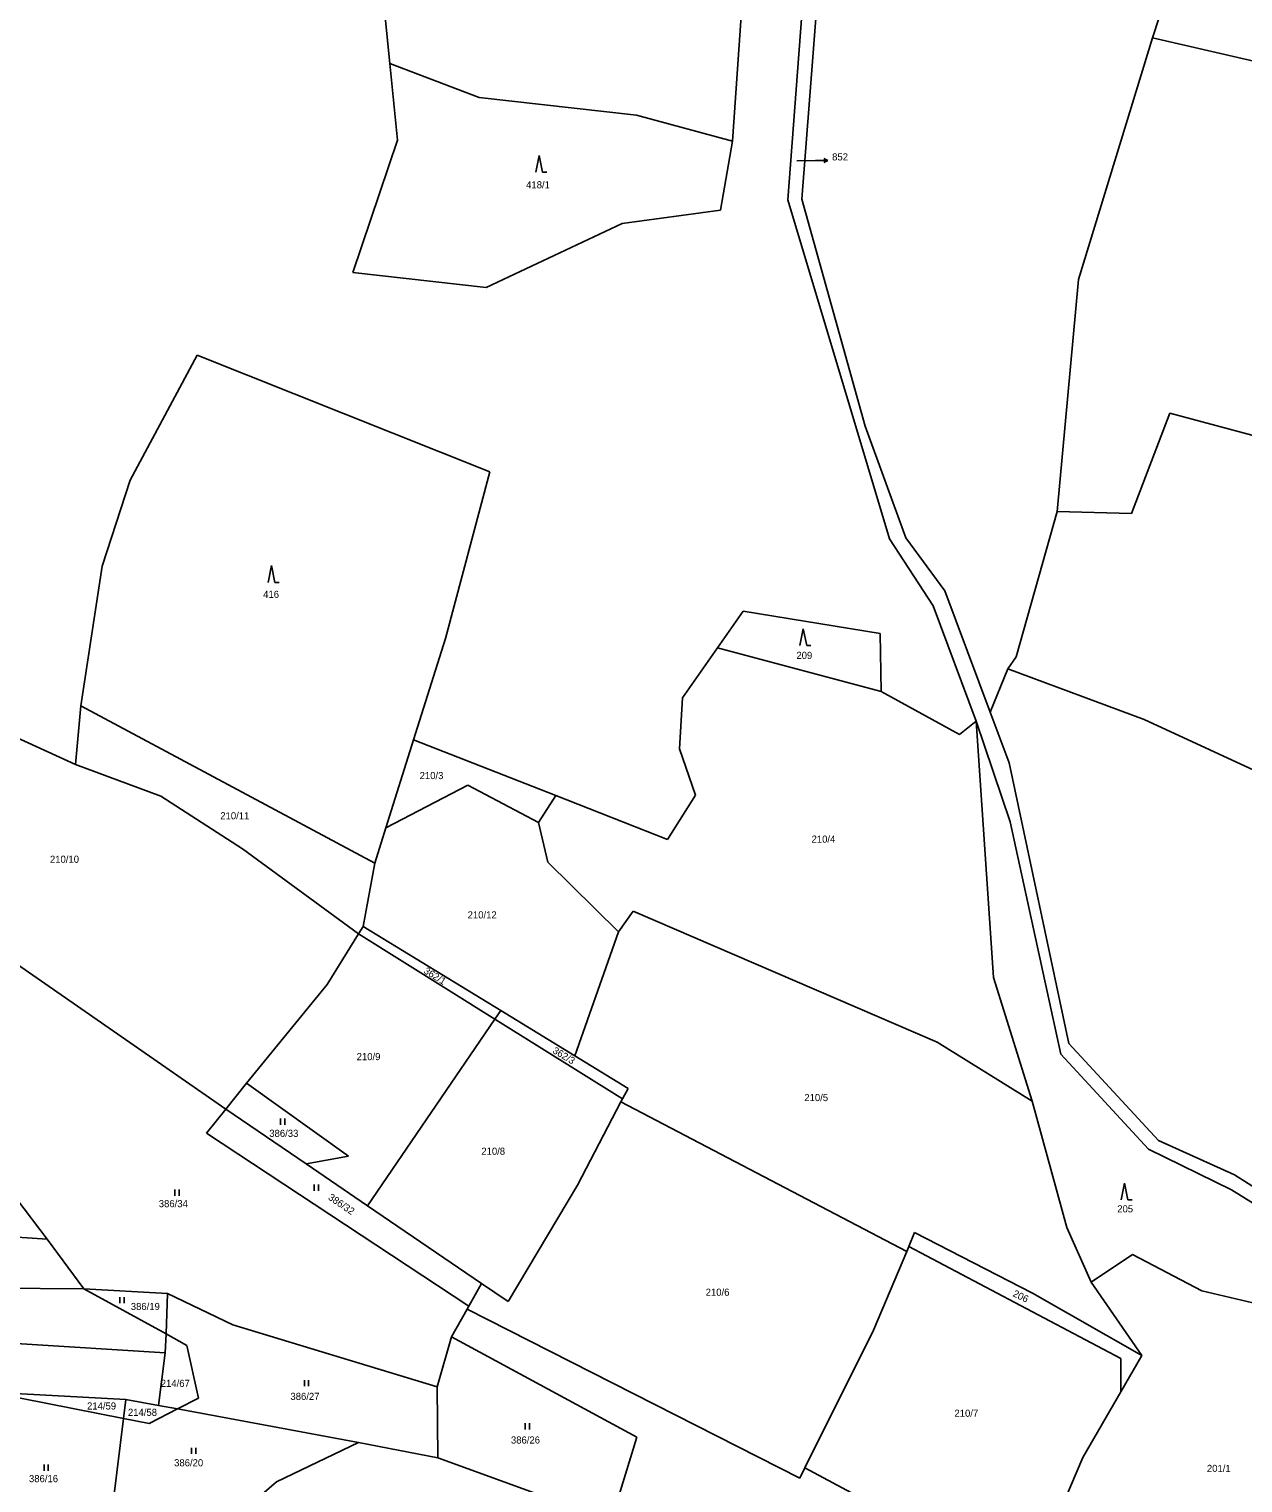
# Model space of a CAD drawing. Extents: x -791032 to -787751, y -1106872 to -1104403.
# Drawn here: x -789521.6 to -789231, y -1105047.4 to -1104699.4 of the extents above; entities that cross this region are included whole.
import ezdxf

# ---------------------------------------------------------------- set-up
doc = ezdxf.new("R2010")
doc.units = 0
for name, color, linetype in [('Komunikace', 7, 'Continuous'), ('Vrstva 1', 7, 'Continuous'), ('Vrstva 14', 7, 'Continuous'), ('Vrstva 16', 7, 'Continuous'), ('Vrstva 23', 7, 'Continuous')]:
    doc.layers.add(name, color=color, linetype=linetype)

msp = doc.modelspace()

# ---------------------------------------------------------------- linework, layer by layer
at = {"layer": 'Komunikace'}
msp.add_line((-789337.83, -1104730.99), (-789333.38, -1104730.91), dxfattribs=at)
at = {"layer": 'Vrstva 1'}
for p, q in [((-789252.66, -1104701.48), (-789219.82, -1104600.12)), ((-789332.71, -1104644.49), (-789339.98, -1104740.32)), ((-789336.62, -1104740.1), (-789329.28, -1104644.72)), ((-789439.94, -1104660.34), (-789435.24, -1104707.64)), ((-789353.27, -1104726.21), (-789350.23, -1104682.32)), ((-789270.39, -1104759.38), (-789252.66, -1104701.48)), ((-789252.66, -1104701.48), (-789130.29, -1104729.79)), ((-789435.24, -1104707.64), (-789413.89, -1104715.81)), ((-789435.24, -1104707.64), (-789433.41, -1104726)), ((-789413.89, -1104715.81), (-789376.18, -1104720)), ((-789376.18, -1104720), (-789353.27, -1104726.21)), ((-789433.41, -1104726), (-789444.13, -1104757.69)), ((-789356.1, -1104742.74), (-789353.27, -1104726.21)), ((-789339.98, -1104740.32), (-789315.67, -1104821.46)), ((-789321.51, -1104794.47), (-789336.62, -1104740.1)), ((-789379.64, -1104745.93), (-789356.1, -1104742.74)), ((-789412.24, -1104761.29), (-789379.64, -1104745.93)), ((-789444.13, -1104757.69), (-789412.24, -1104761.29)), ((-789270.39, -1104759.38), (-789275.52, -1104814.86)), ((-789497.43, -1104807.38), (-789481.42, -1104777.44)), ((-789481.42, -1104777.44), (-789411.33, -1104805.4)), ((-789257.76, -1104815.39), (-789248.58, -1104791.34)), ((-789248.58, -1104791.34), (-789141.03, -1104820.32)), ((-789311.76, -1104821.17), (-789321.51, -1104794.47)), ((-789411.33, -1104805.4), (-789421.97, -1104845.28)), ((-789504.1, -1104828), (-789497.43, -1104807.38)), ((-789275.52, -1104814.86), (-789285.31, -1104849.64)), ((-789275.52, -1104814.86), (-789257.76, -1104815.39)), ((-789315.67, -1104821.46), (-789305.23, -1104837.5)), ((-789302.4, -1104833.9), (-789311.76, -1104821.17)), ((-789509.25, -1104861.37), (-789504.1, -1104828)), ((-789291.52, -1104862.89), (-789302.4, -1104833.9)), ((-789305.23, -1104837.5), (-789294.92, -1104865.1)), ((-789356.8, -1104847.54), (-789350.66, -1104838.78)), ((-789350.66, -1104838.78), (-789317.89, -1104844.12)), ((-789317.89, -1104844.12), (-789317.68, -1104857.94)), ((-789421.97, -1104845.28), (-789429.6, -1104869.53)), ((-789365.17, -1104859.46), (-789356.8, -1104847.54)), ((-789317.68, -1104857.94), (-789356.8, -1104847.54)), ((-789285.31, -1104849.64), (-789287.33, -1104852.58)), ((-789287.33, -1104852.58), (-789291.52, -1104862.89)), ((-789254.72, -1104864.68), (-789287.33, -1104852.58)), ((-789298.88, -1104868.28), (-789317.68, -1104857.94)), ((-789510.51, -1104875.41), (-789509.25, -1104861.37)), ((-789438.89, -1104899.05), (-789509.25, -1104861.37)), ((-789365.17, -1104859.46), (-789365.96, -1104871.69)), ((-789533.85, -1104864.78), (-789510.51, -1104875.41)), ((-789294.92, -1104865.1), (-789298.88, -1104868.28)), ((-789294.92, -1104865.1), (-789286.73, -1104889.2)), ((-789290.79, -1104926.4), (-789294.92, -1104865.1)), ((-789286.98, -1104875.01), (-789291.52, -1104862.89)), ((-789144.83, -1104915.36), (-789254.72, -1104864.68)), ((-789429.6, -1104869.53), (-789436.24, -1104890.62)), ((-789395.55, -1104882.88), (-789429.6, -1104869.53)), ((-789365.96, -1104871.69), (-789362.12, -1104882.76)), ((-789510.51, -1104875.41), (-789490.08, -1104883.03)), ((-789272.7, -1104942.21), (-789286.98, -1104875.01)), ((-789490.08, -1104883.03), (-789470.54, -1104895.61)), ((-789416.63, -1104880.38), (-789436.24, -1104890.62)), ((-789416.63, -1104880.38), (-789399.67, -1104889.33)), ((-789399.67, -1104889.33), (-789395.55, -1104882.88)), ((-789368.81, -1104893.37), (-789395.55, -1104882.88)), ((-789362.12, -1104882.76), (-789368.81, -1104893.37)), ((-789399.67, -1104889.33), (-789397.42, -1104898.85)), ((-789286.73, -1104889.2), (-789274.62, -1104944.78)), ((-789436.24, -1104890.62), (-789438.89, -1104899.05)), ((-789470.54, -1104895.61), (-789442.78, -1104916.01)), ((-789438.89, -1104899.05), (-789441.67, -1104914.21)), ((-789397.42, -1104898.85), (-789380.51, -1104915.46)), ((-789380.51, -1104915.46), (-789377, -1104910.56)), ((-789377, -1104910.56), (-789304.26, -1104941.88)), ((-789442.78, -1104916.01), (-789441.67, -1104914.21)), ((-789408.7, -1104934.35), (-789441.67, -1104914.21)), ((-789532.96, -1104917.4), (-789474.56, -1104957.93)), ((-789442.78, -1104916.01), (-789450.25, -1104928.13)), ((-789410.1, -1104936.4), (-789442.78, -1104916.01)), ((-789391.01, -1104945.15), (-789380.51, -1104915.46)), ((-789469.61, -1104951.75), (-789450.25, -1104928.13)), ((-789281.53, -1104956.02), (-789290.79, -1104926.4)), ((-789408.7, -1104934.35), (-789410.1, -1104936.4)), ((-789391.01, -1104945.15), (-789408.7, -1104934.35)), ((-789410.1, -1104936.4), (-789440.59, -1104981.06)), ((-789379.57, -1104955.45), (-789410.1, -1104936.4)), ((-789304.26, -1104941.88), (-789281.53, -1104956.02)), ((-789251.28, -1104965.46), (-789272.7, -1104942.21)), ((-789378.18, -1104952.99), (-789391.01, -1104945.15)), ((-789274.62, -1104944.78), (-789253.64, -1104967.55)), ((-789474.56, -1104957.93), (-789469.61, -1104951.75)), ((-789445.15, -1104969.16), (-789469.61, -1104951.75)), ((-789390.3, -1104976.11), (-789379.97, -1104956.22)), ((-789379.97, -1104956.22), (-789379.57, -1104955.45)), ((-789379.97, -1104956.22), (-789311.48, -1104991.97)), ((-789379.57, -1104955.45), (-789378.18, -1104952.99)), ((-789273.17, -1104986.28), (-789281.53, -1104956.02)), ((-789474.56, -1104957.93), (-789479.19, -1104963.72)), ((-789474.56, -1104957.93), (-789455.3, -1104971.04)), ((-789416.34, -1105005.05), (-789479.19, -1104963.72)), ((-789233.09, -1104973.66), (-789251.28, -1104965.46)), ((-789445.15, -1104969.16), (-789455.3, -1104971.04)), ((-789253.64, -1104967.55), (-789233.79, -1104977.26)), ((-789455.3, -1104971.04), (-789440.59, -1104981.06)), ((-789194.82, -1104998.08), (-789233.09, -1104973.66)), ((-789406.97, -1105003.94), (-789390.3, -1104976.11)), ((-789517.33, -1104989.08), (-789524.52, -1104979.45)), ((-789233.79, -1104977.26), (-789193.97, -1105002.1)), ((-789634.18, -1104981.42), (-789517.33, -1104989.08)), ((-789440.59, -1104981.06), (-789413.29, -1104999.64)), ((-789310.99, -1104990.81), (-789309.67, -1104987.43)), ((-789281.43, -1105001.95), (-789309.67, -1104987.43)), ((-789267.38, -1104999.38), (-789273.17, -1104986.28)), ((-789508.48, -1105000.93), (-789517.33, -1104989.08)), ((-789310.99, -1104990.81), (-789311.48, -1104991.97)), ((-789260.31, -1105017.58), (-789310.99, -1104990.81)), ((-789311.48, -1104991.97), (-789319.46, -1105010.8)), ((-789267.38, -1104999.38), (-789257.5, -1104992.73)), ((-789257.5, -1104992.73), (-789240.88, -1105001.4)), ((-789611.54, -1105000.15), (-789508.48, -1105000.93)), ((-789488.84, -1105011.73), (-789508.48, -1105000.93)), ((-789508.48, -1105000.93), (-789488.47, -1105002.04)), ((-789416.34, -1105005.05), (-789413.29, -1104999.64)), ((-789413.29, -1104999.64), (-789406.97, -1105003.94)), ((-789255.24, -1105016.86), (-789267.38, -1104999.38)), ((-789240.88, -1105001.4), (-789221.84, -1105005.93)), ((-789488.47, -1105002.04), (-789488.84, -1105011.73)), ((-789488.47, -1105002.04), (-789472.87, -1105009.56)), ((-789255.24, -1105016.86), (-789281.43, -1105001.95)), ((-789420.51, -1105012.44), (-789416.79, -1105005.84)), ((-789416.79, -1105005.84), (-789416.34, -1105005.05)), ((-789337.15, -1105046.24), (-789416.79, -1105005.84)), ((-789488.84, -1105011.73), (-789489.01, -1105016.25)), ((-789483.86, -1105014.47), (-789488.84, -1105011.73)), ((-789472.87, -1105009.56), (-789423.9, -1105024.43)), ((-789319.46, -1105010.8), (-789335.91, -1105043.8)), ((-789524.7, -1105014.01), (-789489.01, -1105016.25)), ((-789481.09, -1105027.09), (-789483.86, -1105014.47)), ((-789420.51, -1105012.44), (-789423.9, -1105024.43)), ((-789420.51, -1105012.44), (-789376.17, -1105036.47)), ((-789490.64, -1105028.87), (-789489.01, -1105016.25)), ((-789260.31, -1105025.63), (-789255.24, -1105016.86)), ((-789260.31, -1105017.58), (-789260.31, -1105025.63)), ((-789530.7, -1105025.7), (-789499.01, -1105031.98)), ((-789530.7, -1105025.7), (-789498.45, -1105027.43)), ((-789423.9, -1105024.43), (-789423.8, -1105041.43)), ((-789269.38, -1105041.33), (-789260.31, -1105025.63)), ((-789499.01, -1105031.98), (-789498.45, -1105027.43)), ((-789498.45, -1105027.43), (-789490.64, -1105028.87)), ((-789490.64, -1105028.87), (-789486.12, -1105029.7)), ((-789486.12, -1105029.7), (-789481.09, -1105027.09)), ((-789501.39, -1105051.37), (-789499.01, -1105031.98)), ((-789499.01, -1105031.98), (-789492.85, -1105033.2)), ((-789492.85, -1105033.2), (-789486.12, -1105029.7)), ((-789486.12, -1105029.7), (-789442.76, -1105037.73)), ((-789462.42, -1105047.11), (-789442.76, -1105037.73)), ((-789423.8, -1105041.43), (-789442.76, -1105037.73)), ((-789382.28, -1105056.43), (-789376.17, -1105036.47)), ((-789382.28, -1105056.43), (-789423.8, -1105041.43)), ((-789278.51, -1105062.82), (-789269.38, -1105041.33)), ((-789337.15, -1105046.24), (-789335.91, -1105043.8)), ((-789282.53, -1105072.29), (-789335.91, -1105043.8)), ((-789462.42, -1105047.11), (-789471.88, -1105055.3))]:
    msp.add_line(p, q, dxfattribs=at)
at = {"layer": 'Vrstva 16'}
for p, q in [((-789333.38, -1104730.91), (-789330.38, -1104730.857)), ((-789330.38, -1104730.857), (-789331.389, -1104730.375)), ((-789330.38, -1104730.857), (-789331.371, -1104731.375))]:
    msp.add_line(p, q, dxfattribs=at)
at = {"layer": 'Vrstva 23'}
for p, q in [((-789400.32, -1104733.65), (-789399.52, -1104729.65)), ((-789399.52, -1104729.65), (-789398.72, -1104733.65)), ((-789398.72, -1104733.65), (-789397.72, -1104733.65)), ((-789464.37, -1104831.85), (-789463.57, -1104827.85)), ((-789463.57, -1104827.85), (-789462.77, -1104831.85)), ((-789462.77, -1104831.85), (-789461.77, -1104831.85)), ((-789337.08, -1104846.96), (-789336.28, -1104842.96)), ((-789336.28, -1104842.96), (-789335.48, -1104846.96)), ((-789335.48, -1104846.96), (-789334.48, -1104846.96)), ((-789461.41, -1104961.7), (-789461.41, -1104960.2)), ((-789460.41, -1104960.2), (-789460.41, -1104961.7)), ((-789453.35, -1104977.46), (-789453.35, -1104975.96)), ((-789452.35, -1104975.96), (-789452.35, -1104977.46)), ((-789260.18, -1104979.66), (-789259.38, -1104975.66)), ((-789259.38, -1104975.66), (-789258.58, -1104979.66)), ((-789486.73, -1104978.7), (-789486.73, -1104977.2)), ((-789485.73, -1104977.2), (-789485.73, -1104978.7)), ((-789258.58, -1104979.66), (-789257.58, -1104979.66)), ((-789499.89, -1105004.4), (-789499.89, -1105002.9)), ((-789498.89, -1105002.9), (-789498.89, -1105004.4)), ((-789455.72, -1105024.27), (-789455.72, -1105022.77)), ((-789454.72, -1105022.77), (-789454.72, -1105024.27)), ((-789402.83, -1105034.58), (-789402.83, -1105033.08)), ((-789401.83, -1105033.08), (-789401.83, -1105034.58)), ((-789482.73, -1105040.47), (-789482.73, -1105038.97)), ((-789481.73, -1105038.97), (-789481.73, -1105040.47)), ((-789518.02, -1105044.52), (-789518.02, -1105043.02)), ((-789517.02, -1105043.02), (-789517.02, -1105044.52))]:
    msp.add_line(p, q, dxfattribs=at)

# ---------------------------------------------------------------- texts
at = {"layer": 'Vrstva 14'}
for s, height, p in [('852', 0.1, (-789337.96, -1104730.99)), ('418/1', 1.7, (-789402.632, -1104737.54)), ('416', 1.7, (-789465.586, -1104835.56)), ('209', 1.7, (-789337.936, -1104850.17)), ('210/3', 1.7, (-789428.132, -1104878.94)), ('210/11', 1.7, (-789475.849, -1104888.56)), ('210/4', 1.7, (-789334.308, -1104894.15)), ('210/10', 1.7, (-789516.624, -1104898.97)), ('210/12', 1.7, (-789416.635, -1104912.28)), ('210/9', 1.7, (-789443.202, -1104946.21)), ('210/5', 1.7, (-789336.038, -1104956.01)), ('386/33', 1.7, (-789464.12, -1104964.57)), ('210/8', 1.7, (-789413.362, -1104968.85)), ('386/34', 1.7, (-789490.576, -1104981.4)), ('205', 1.7, (-789261.132, -1104982.64)), ('210/6', 1.7, (-789359.652, -1105002.6)), ('386/19', 1.7, (-789497.273, -1105006.01)), ('214/67', 1.7, (-789490.095, -1105024.41)), ('386/27', 1.7, (-789459.056, -1105027.53)), ('214/59', 1.7, (-789507.745, -1105029.83)), ('214/58', 1.7, (-789497.955, -1105031.35)), ('210/7', 1.7, (-789300.099, -1105031.57)), ('386/26', 1.7, (-789406.27, -1105037.97)), ('386/20', 1.7, (-789486.899, -1105043.42)), ('201/1', 1.7, (-789239.665, -1105044.77)), ('386/16', 1.7, (-789521.643, -1105047.22))]:
    msp.add_text(s, height=height, dxfattribs=at).set_placement(p)
for s, rotation, p in [('362/1', 328.29516, (-789427.306, -1104925.274)), ('362/3', 329.28714, (-789396.478, -1104944.377)), ('386/32', 325.66707, (-789450.189, -1104979.412)), ('206', 333.58419, (-789286.295, -1105002.628))]:
    msp.add_text(s, height=1.7, rotation=rotation, dxfattribs=at).set_placement(p)
at = {"layer": 'Vrstva 16'}
msp.add_text('852', height=1.7, dxfattribs=at).set_placement((-789329.38, -1104730.86))

doc.saveas('drawing.dxf')
